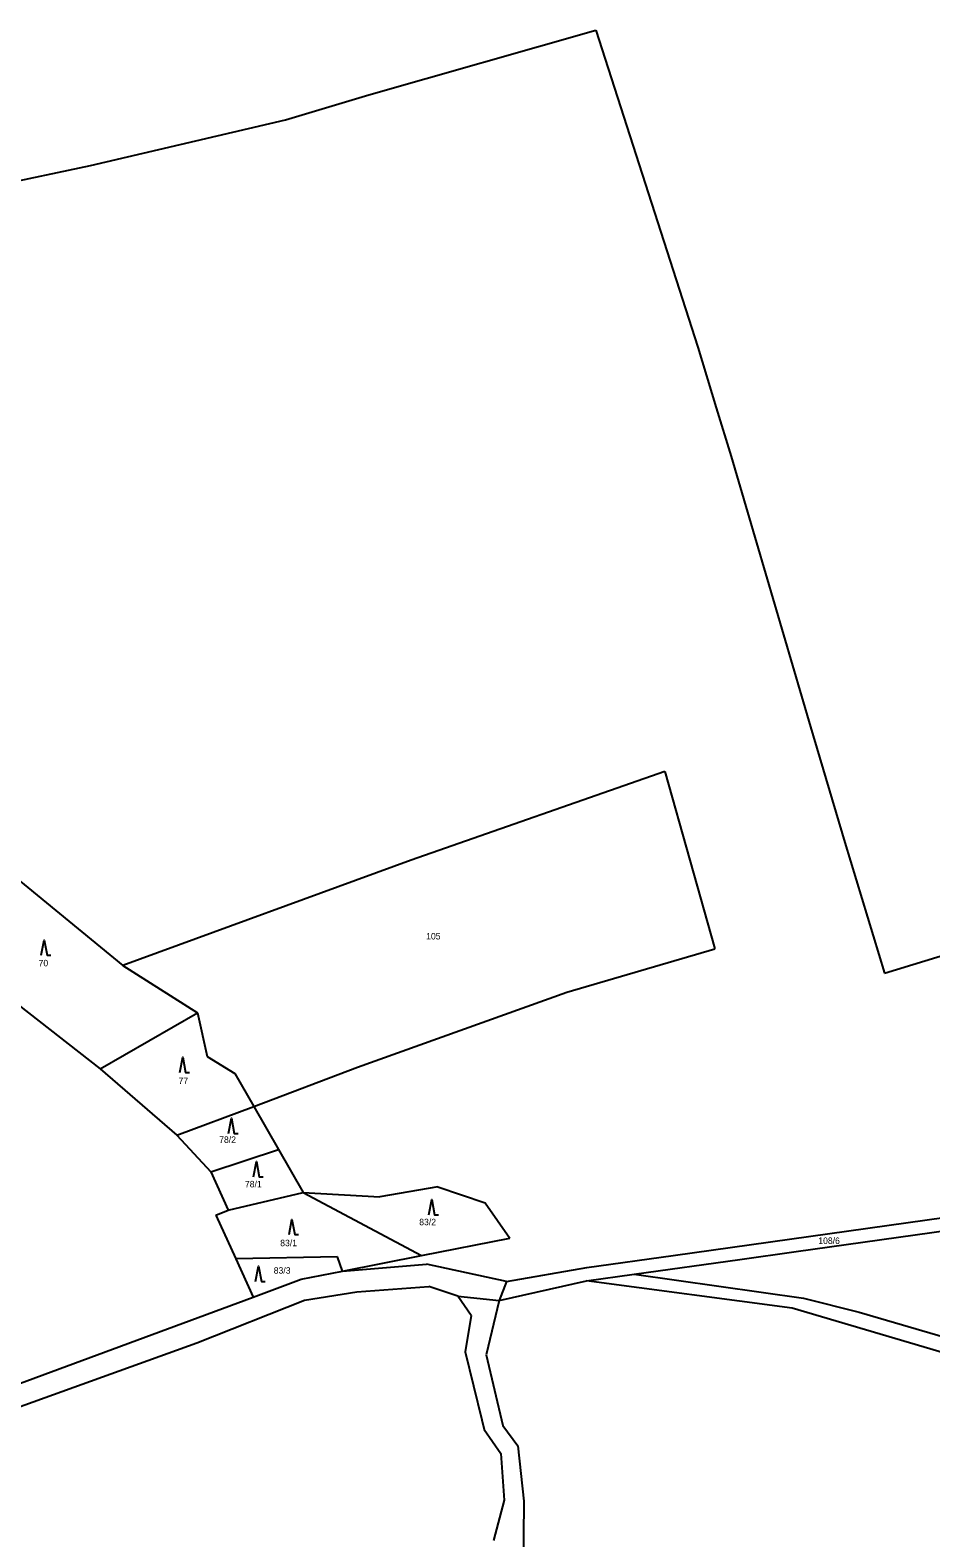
# Model space of a CAD drawing. Extents: x -780000 to -777378, y -1011169 to -1009297.
# Drawn here: x -778666.9 to -778429.6, y -1010110.5 to -1009713.3 of the extents above; entities that cross this region are included whole.
import ezdxf

# ---------------------------------------------------------------- set-up
doc = ezdxf.new("R2010")
doc.units = 0
for name, color, linetype in [('Default', 7, 'Continuous'), ('KN_HRANICE', 7, 'Continuous'), ('KN_KULTURY', 7, 'Continuous'), ('KN_PARCELY', 7, 'Continuous')]:
    doc.layers.add(name, color=color, linetype=linetype)

# ---------------------------------------------------------------- blocks, each defined once
blk = doc.blocks.new('308')
at = {"layer": 'Default'}
blk.add_lwpolyline([(-0.75, 0), (0, 4), (0.75, 0), (1.75, 0)], dxfattribs=at)

msp = doc.modelspace()

# ---------------------------------------------------------------- linework, layer by layer
at = {"layer": 'KN_HRANICE'}
for p, q in [((-778577.68, -1009730.31), (-778517.87, -1009713.29)), ((-778517.87, -1009713.29), (-778491.03, -1009796.82)), ((-778599.62, -1009736.93), (-778577.68, -1009730.31)), ((-778650.92, -1009748.98), (-778599.62, -1009736.93)), ((-778682.79, -1009755.72), (-778650.92, -1009748.98)), ((-778491.03, -1009796.82), (-778486.17, -1009812.8)), ((-778486.17, -1009812.8), (-778482.26, -1009825.63)), ((-778482.26, -1009825.63), (-778477.95, -1009840.27)), ((-778477.95, -1009840.27), (-778461.29, -1009896.85)), ((-778461.29, -1009896.85), (-778452.32, -1009927.34)), ((-778499.66, -1009908.62), (-778566.52, -1009931.95)), ((-778499.66, -1009908.62), (-778486.49, -1009955.32)), ((-778452.32, -1009927.34), (-778441.85, -1009961.74)), ((-778566.52, -1009931.95), (-778642.47, -1009959.73)), ((-778670.88, -1009936.37), (-778642.47, -1009959.73)), ((-778441.85, -1009961.74), (-778409.93, -1009951.93)), ((-778525.48, -1009966.76), (-778486.49, -1009955.32)), ((-778642.47, -1009959.73), (-778622.81, -1009972.22)), ((-778580.61, -1009986.47), (-778525.48, -1009966.76)), ((-778670.06, -1009969.95), (-778648.43, -1009986.95)), ((-778648.43, -1009986.95), (-778622.81, -1009972.22)), ((-778622.81, -1009972.22), (-778620.25, -1009983.66)), ((-778620.25, -1009983.66), (-778612.91, -1009988.16)), ((-778648.43, -1009986.95), (-778628.19, -1010004.45)), ((-778612.91, -1009988.16), (-778607.95, -1009996.84)), ((-778607.95, -1009996.84), (-778580.61, -1009986.47)), ((-778628.19, -1010004.45), (-778607.95, -1009996.84)), ((-778607.95, -1009996.84), (-778601.46, -1010008.2)), ((-778628.19, -1010004.45), (-778619.27, -1010014.08)), ((-778619.27, -1010014.08), (-778601.46, -1010008.2)), ((-778601.46, -1010008.2), (-778594.98, -1010019.53)), ((-778619.27, -1010014.08), (-778614.73, -1010024.15)), ((-778497.51, -1010036.07), (-778348.28, -1010015.11)), ((-778614.73, -1010024.15), (-778594.98, -1010019.53)), ((-778594.98, -1010019.53), (-778574.79, -1010020.66)), ((-778594.98, -1010019.53), (-778563.77, -1010036.13)), ((-778559.52, -1010017.99), (-778574.79, -1010020.66)), ((-778559.52, -1010017.99), (-778547, -1010022.25)), ((-778465.13, -1010035.06), (-778347.45, -1010018.54)), ((-778617.96, -1010025.49), (-778614.73, -1010024.15)), ((-778547, -1010022.25), (-778540.53, -1010031.53)), ((-778617.96, -1010025.49), (-778612.72, -1010037)), ((-778563.77, -1010036.13), (-778540.53, -1010031.53)), ((-778585.92, -1010036.44), (-778612.72, -1010037)), ((-778584.59, -1010040.25), (-778585.92, -1010036.44)), ((-778584.59, -1010040.25), (-778563.77, -1010036.13)), ((-778520.25, -1010039.26), (-778497.51, -1010036.07)), ((-778479.97, -1010037.14), (-778465.13, -1010035.06)), ((-778612.72, -1010037), (-778608.15, -1010047.05)), ((-778595.49, -1010042.35), (-778584.59, -1010040.25)), ((-778584.59, -1010040.25), (-778562.47, -1010038.37)), ((-778541.4, -1010042.99), (-778562.47, -1010038.37)), ((-778541.4, -1010042.99), (-778520.25, -1010039.26)), ((-778507.76, -1010041.04), (-778479.97, -1010037.14)), ((-778608.15, -1010047.05), (-778595.49, -1010042.35)), ((-778580.85, -1010045.72), (-778561.81, -1010044.31)), ((-778554.23, -1010046.82), (-778561.81, -1010044.31)), ((-778543.3, -1010047.94), (-778520.34, -1010042.8)), ((-778541.4, -1010042.99), (-778543.3, -1010047.94)), ((-778520.34, -1010042.8), (-778507.76, -1010041.04)), ((-778466.13, -1010049.97), (-778520.34, -1010042.8)), ((-778507.76, -1010041.04), (-778463.16, -1010047.36)), ((-778695.97, -1010079.62), (-778608.15, -1010047.05)), ((-778622.94, -1010059.11), (-778594.64, -1010047.86)), ((-778594.64, -1010047.86), (-778580.85, -1010045.72)), ((-778550.67, -1010051.95), (-778554.23, -1010046.82)), ((-778554.23, -1010046.82), (-778543.3, -1010047.94)), ((-778543.3, -1010047.94), (-778546.71, -1010062.28)), ((-778463.16, -1010047.36), (-778448.54, -1010051.05)), ((-778550.67, -1010051.95), (-778552.26, -1010061.45)), ((-778423.7, -1010062.57), (-778466.13, -1010049.97)), ((-778448.54, -1010051.05), (-778413.41, -1010061.34)), ((-778684.92, -1010081.46), (-778622.94, -1010059.11)), ((-778552.26, -1010061.45), (-778547.93, -1010079.4)), ((-778546.71, -1010062.28), (-778542.32, -1010080.9)), ((-778547.93, -1010079.4), (-778547.31, -1010081.95)), ((-778547.31, -1010081.95), (-778542.87, -1010088.3)), ((-778542.32, -1010080.9), (-778538.43, -1010086.26)), ((-778542.87, -1010088.3), (-778541.98, -1010100.57)), ((-778538.43, -1010086.26), (-778536.83, -1010100.87)), ((-778541.98, -1010100.57), (-778544.84, -1010111.19)), ((-778536.83, -1010100.87), (-778537.2, -1010135.97))]:
    msp.add_line(p, q, dxfattribs=at)

# ---------------------------------------------------------------- block references
at = {"layer": 'KN_KULTURY'}
for p in [(-778663.16, -1009957.01), (-778626.66, -1009987.86), (-778613.84, -1010003.94), (-778607.26, -1010015.36), (-778561.1, -1010025.37), (-778597.9, -1010030.61), (-778606.71, -1010042.92)]:
    msp.add_blockref('308', p, dxfattribs=at)

# ---------------------------------------------------------------- texts
at = {"layer": 'KN_PARCELY'}
for s, p in [('105', (-778562.56, -1009952.85)), ('70', (-778664.63, -1009959.92)), ('77', (-778627.77, -1009990.93)), ('78/2', (-778617.07, -1010006.44)), ('78/1', (-778610.29, -1010018.15)), ('83/2', (-778564.38, -1010028.14)), ('83/1', (-778600.99, -1010033.66)), ('108/6', (-778459.28, -1010033.06)), ('83/3', (-778602.7, -1010040.89))]:
    msp.add_text(s, height=1.7, dxfattribs=at).set_placement(p)

doc.saveas('drawing.dxf')
